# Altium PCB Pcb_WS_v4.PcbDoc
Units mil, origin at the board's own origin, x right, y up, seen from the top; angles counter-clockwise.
Board outline 3890 x 3890 mil, 2 copper layers (Top Layer, Bottom Layer); 75 components, 61 nets, 248 pads, 169 vias.
Unrouted connection lines stored in the file: 133.
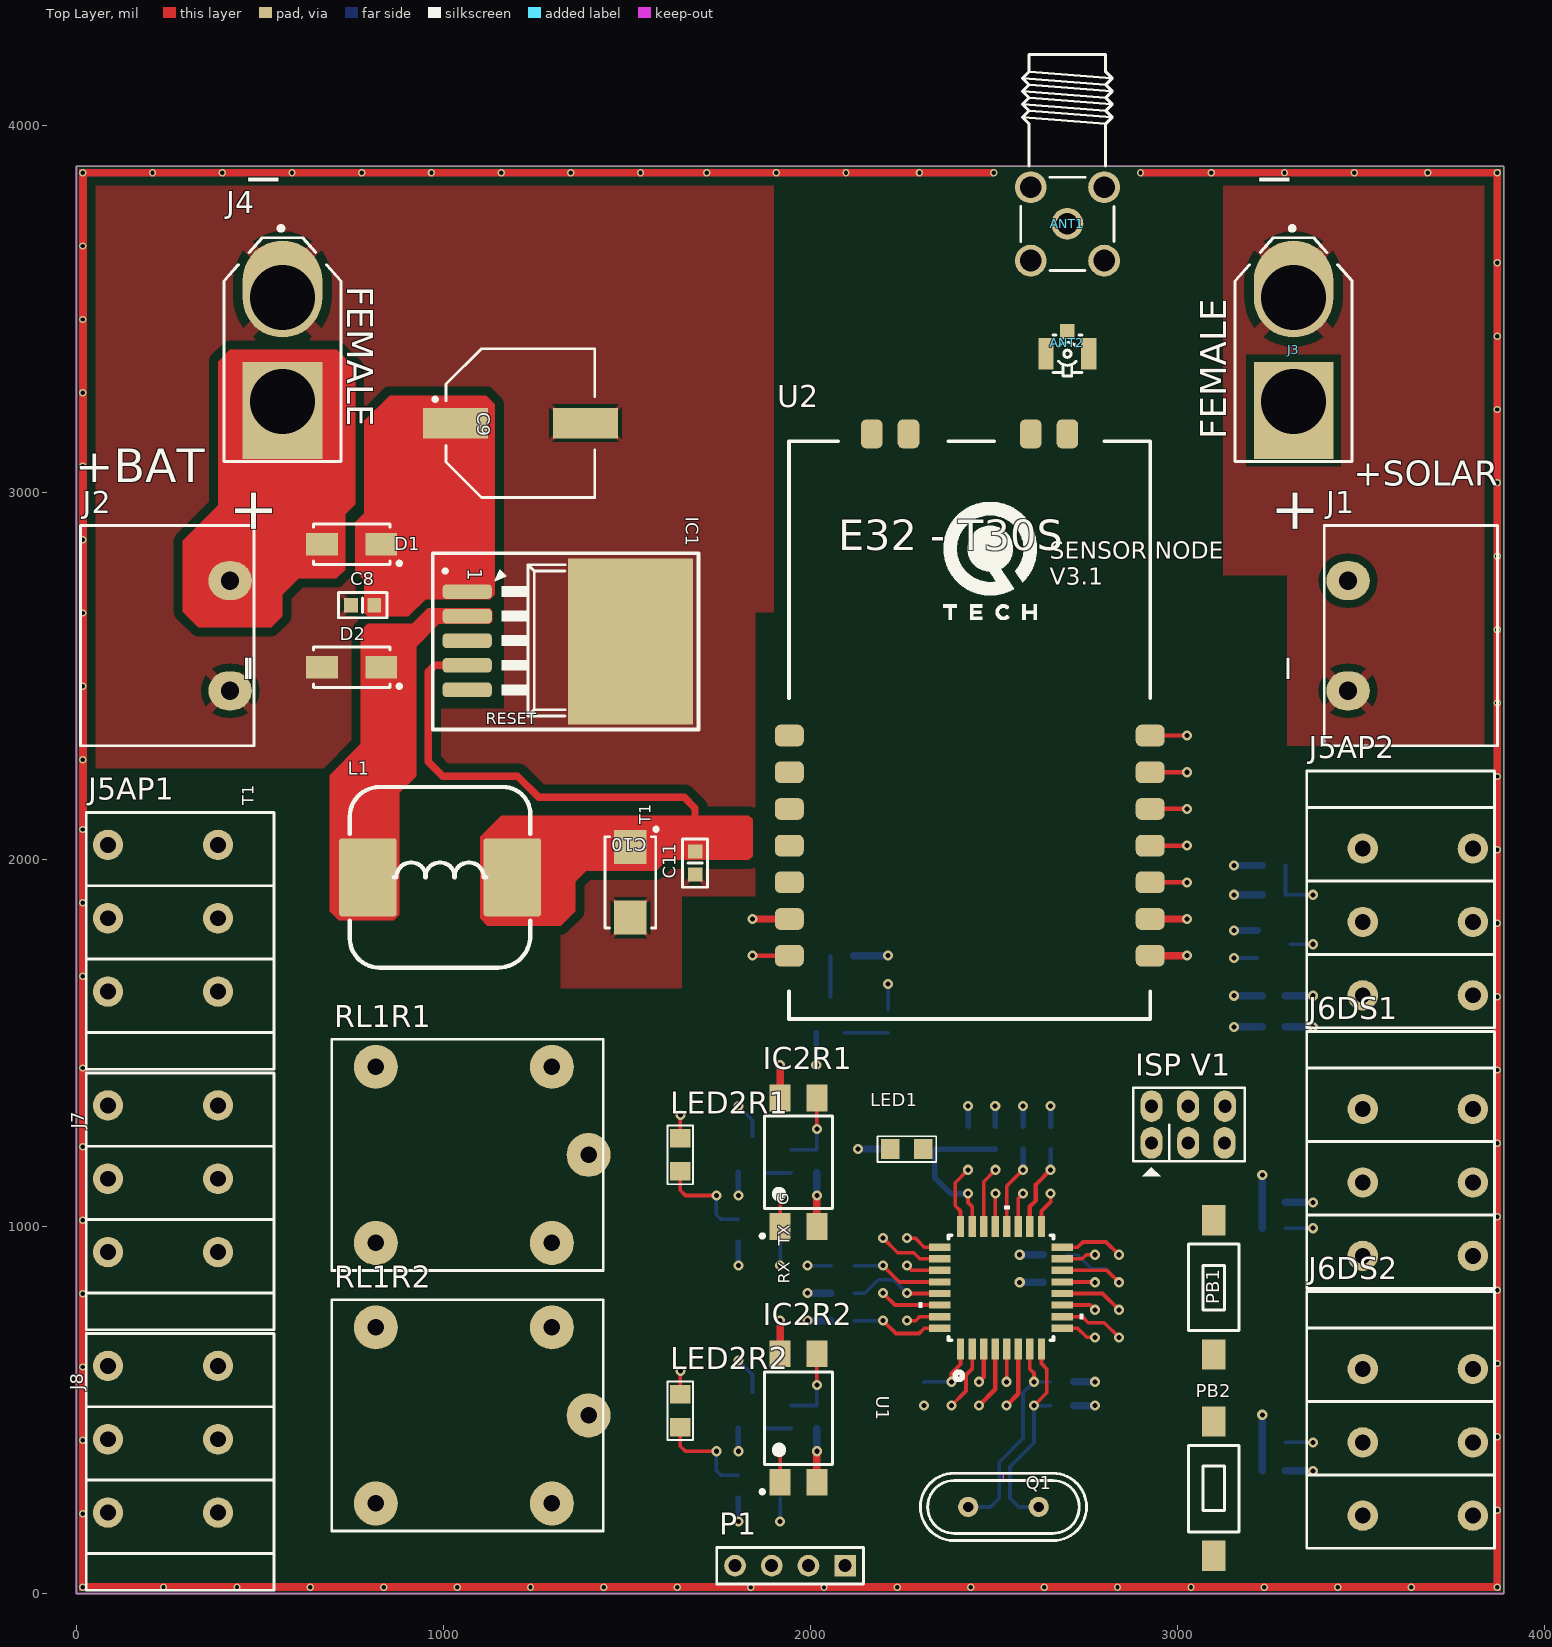
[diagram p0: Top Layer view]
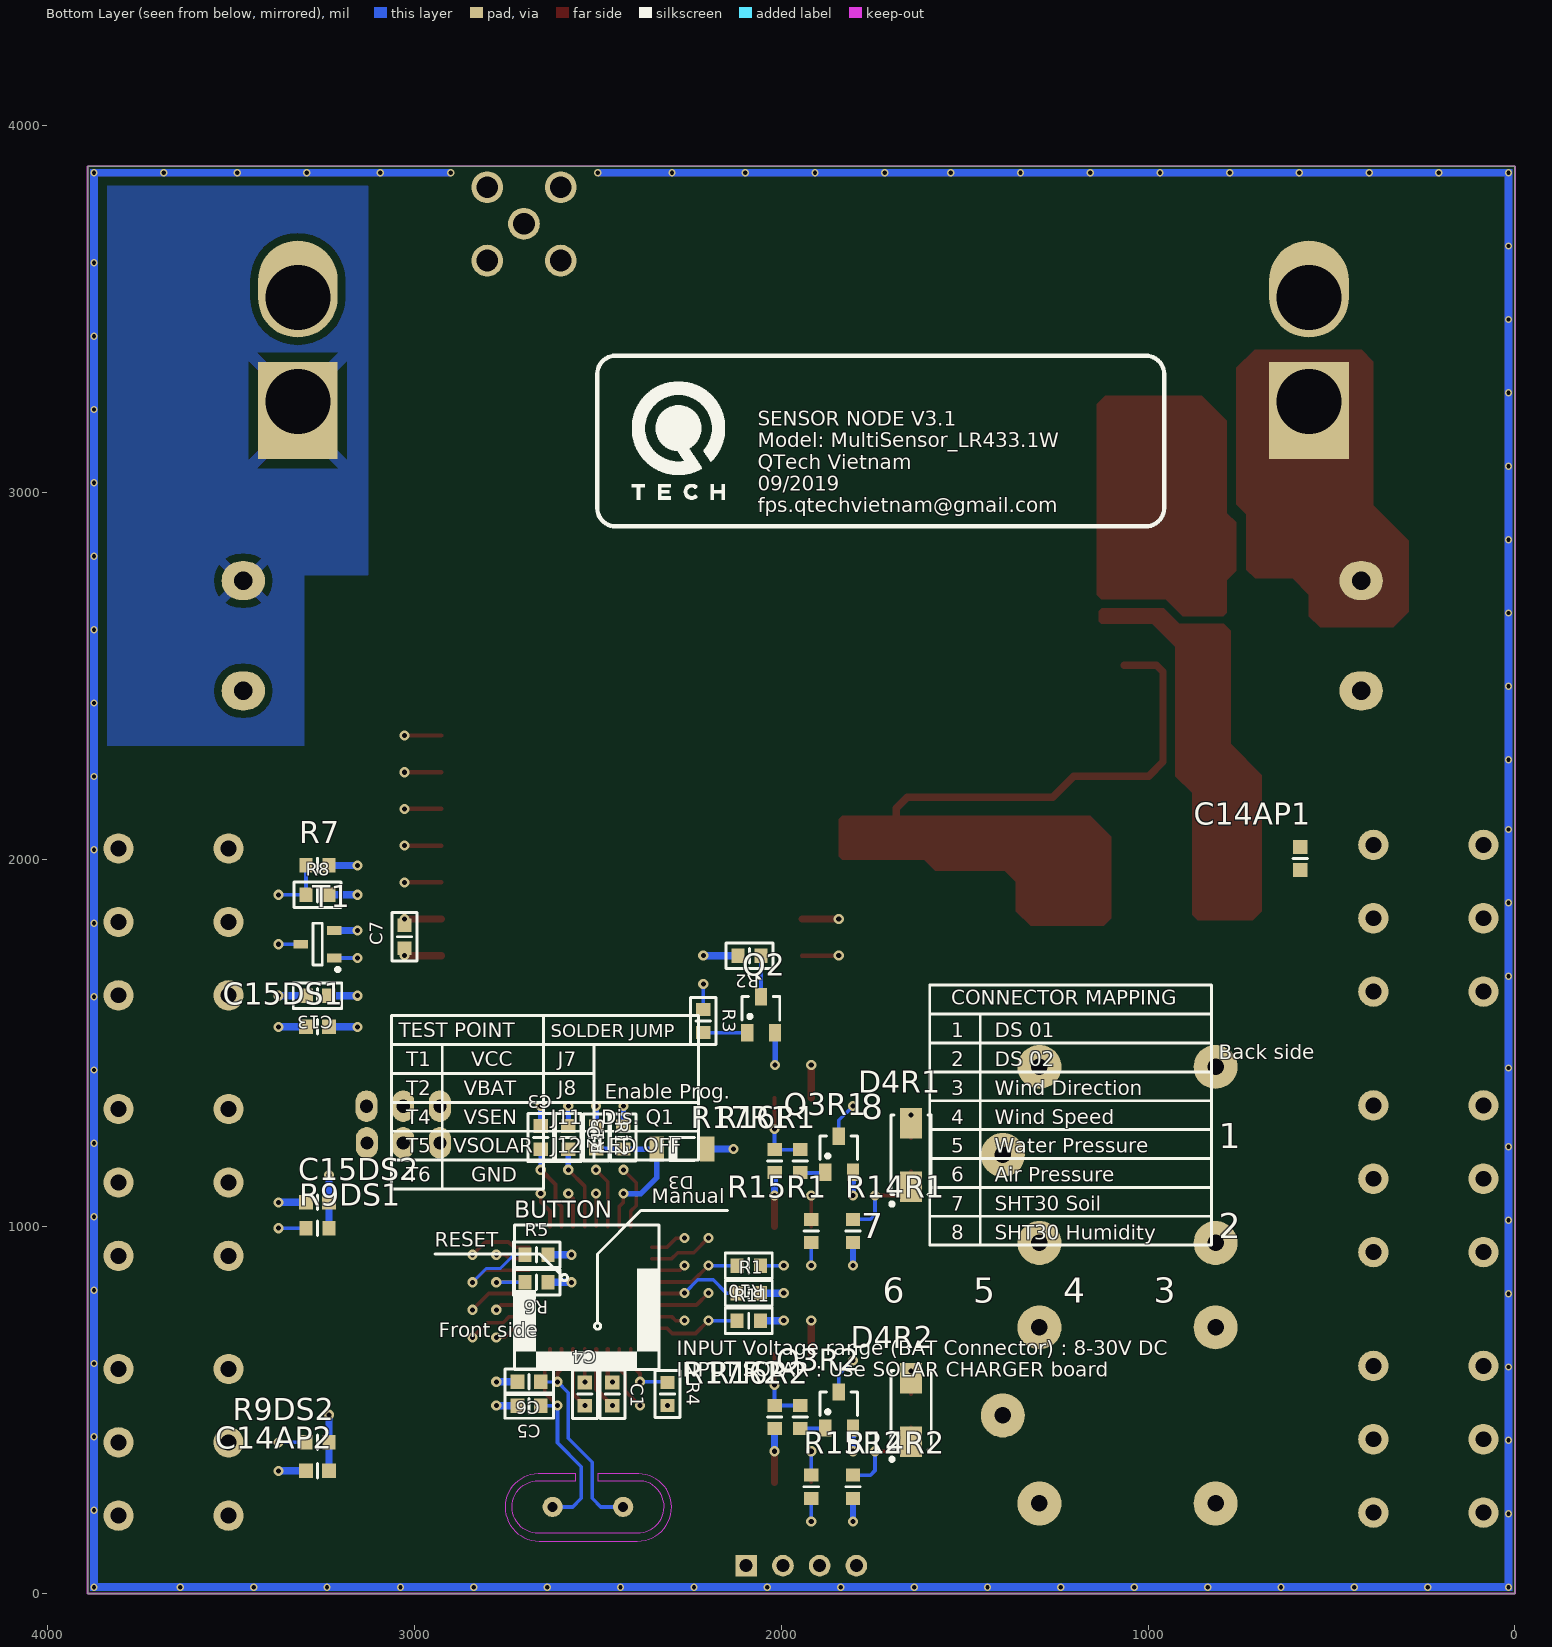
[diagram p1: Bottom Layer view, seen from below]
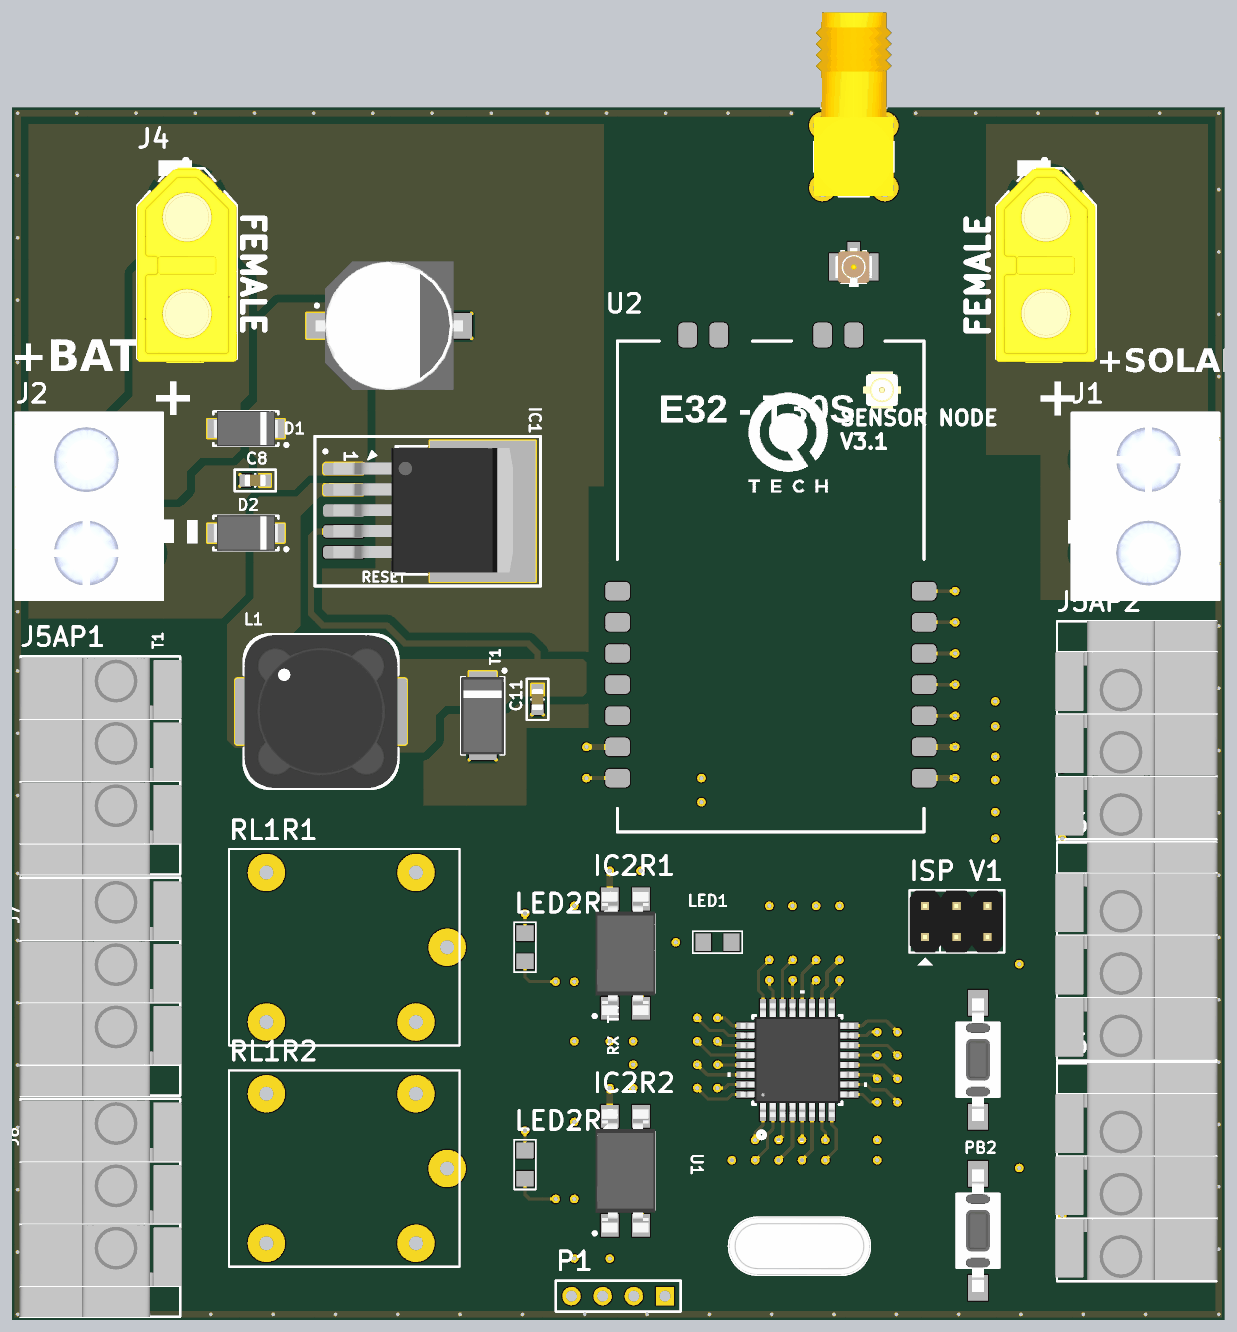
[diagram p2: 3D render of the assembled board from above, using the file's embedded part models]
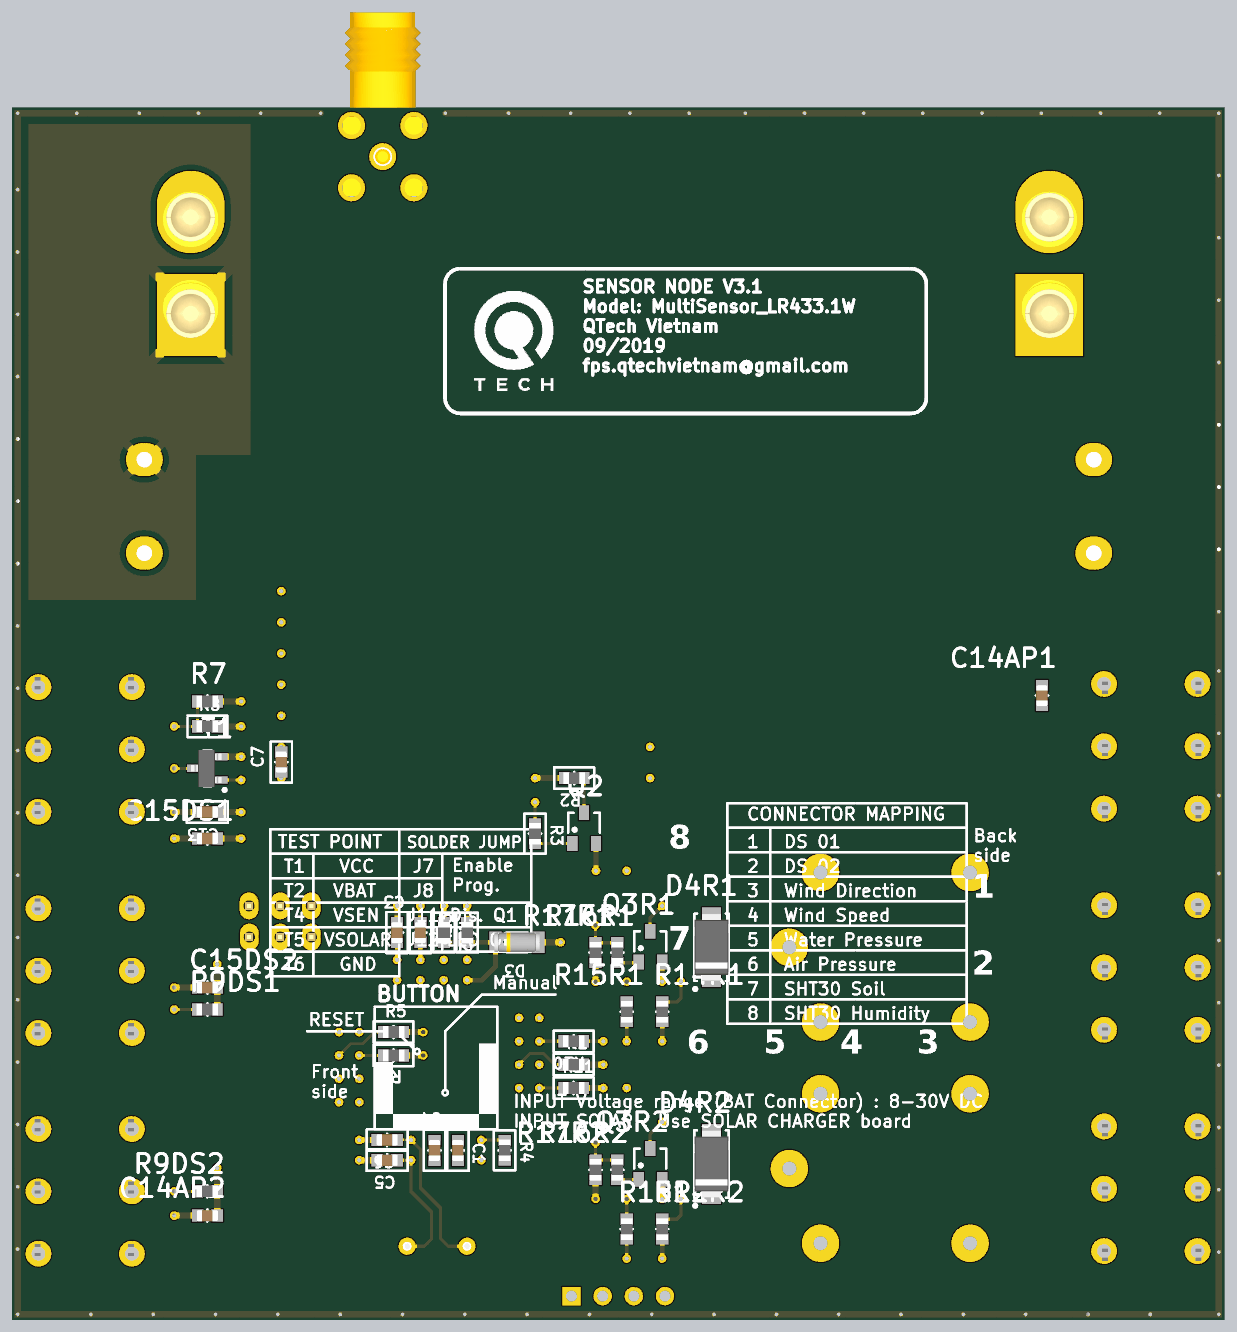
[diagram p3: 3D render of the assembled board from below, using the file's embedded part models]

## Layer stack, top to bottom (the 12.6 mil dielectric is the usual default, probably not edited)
Top Solder: solder mask 0.4, Solder Resist, Dk 3.5
Top Layer: signal copper 1.4
Dielectric 1: dielectric 12.6, FR-4, Dk 4.8
Bottom Layer: signal copper 1.4
Bottom Solder: solder mask 0.4, Solder Resist, Dk 3.5

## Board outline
0,0 0,3890 3890,3890 3890,0

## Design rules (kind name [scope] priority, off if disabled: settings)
Clearance Keep_Out [OnLayer('Keep-Out Layer')] p1: gap=5 ignorepadtopadclearanceinfootprint=FALSE
Clearance [All] p2: gap=10 ignorepadtopadclearanceinfootprint=FALSE except(15: SMDPad-Poly; 20: THPad-Poly; 25: Track-Poly Poly-Poly Poly-Region)
ComponentClearance KF-conn_Clearance [InComponentClass('KF_conn') vs InComponentClass('KF_conn')] p1: gap=5 collisioncheckmode=3 verticalgap=0 showdistances=FALSE
ComponentClearance HS_Comp_Clearance [InComponentClass('HS_Comp') vs IsComponent] p2: gap=165 collisioncheckmode=3 verticalgap=0 showdistances=FALSE
ComponentClearance IC_Comp_Clearance [InComponentClass('IC_Comp') vs IsComponent] p3: gap=150 collisioncheckmode=3 verticalgap=0 showdistances=FALSE
ComponentClearance conn-th_Clearance [InComponentClass('conn-th') vs IsComponent and not InComponentClass('conn-th')] p4: gap=150 collisioncheckmode=3 verticalgap=0 showdistances=FALSE
ComponentClearance chip-ge_Clearance [InComponentClass('chip-ge') vs InAnyComponent] p5: gap=75 collisioncheckmode=3 verticalgap=0 showdistances=FALSE
ComponentClearance chip-0603_Clearance [InComponentClass('chip-0603') vs IsComponent] p6: gap=25 collisioncheckmode=3 verticalgap=0 showdistances=FALSE
PolygonConnect [All] p1: thpad.connectstyle=Relief thpad.reliefconductorwidth=13.78 thpad.reliefentries=4 thpad.polygonreliefangle="45 Angle" thpad.airgapwidth=10 smdpad.connectstyle=Relief smdpad.reliefconductorwidth=11.81 smdpad.reliefentries=4 smdpad.polygonreliefangle="45 Angle" smdpad.airgapwidth=10 via.connectstyle=Direct via.reliefconductorwidth=10 via.reliefentries=4 via.polygonreliefangle="90 Angle" via.airgapwidth=10
RoomDefinition Top_Level [InComponentClass('Top_Level')] p1: confinementstyle=ConfineIn formatcopy=TRUE lockcomponents=FALSE outline -1409.14,-1234.46 590.86,-1234.46 590.86,-234.46 -1409.14,-234.46
RoomDefinition R2 [InComponentClass('R2')] p2: confinementstyle=ConfineIn formatcopy=TRUE lockcomponents=FALSE outline -1409.14,-1234.46 590.86,-1234.46 590.86,-234.46 -1409.14,-234.46
RoomDefinition R1 [InComponentClass('R1')] p3: confinementstyle=ConfineIn formatcopy=TRUE lockcomponents=FALSE outline -1409.14,-1234.46 590.86,-1234.46 590.86,-234.46 -1409.14,-234.46
RoomDefinition PWR [InComponentClass('PWR')] p4: confinementstyle=ConfineIn formatcopy=TRUE lockcomponents=FALSE outline -1409.14,-1234.46 590.86,-1234.46 590.86,-234.46 -1409.14,-234.46
RoomDefinition Main [InComponentClass('Main')] p5: confinementstyle=ConfineIn formatcopy=TRUE lockcomponents=FALSE outline -1409.14,-1234.46 590.86,-1234.46 590.86,-234.46 -1409.14,-234.46
RoomDefinition Lora [InComponentClass('Lora')] p6: confinementstyle=ConfineIn formatcopy=TRUE lockcomponents=FALSE outline -1409.14,-1234.46 590.86,-1234.46 590.86,-234.46 -1409.14,-234.46
RoomDefinition DS2 [InComponentClass('DS2')] p7: confinementstyle=ConfineIn formatcopy=TRUE lockcomponents=FALSE outline -1409.14,-1234.46 590.86,-1234.46 590.86,-234.46 -1409.14,-234.46
RoomDefinition DS1 [InComponentClass('DS1')] p8: confinementstyle=ConfineIn formatcopy=TRUE lockcomponents=FALSE outline -1409.14,-1234.46 590.86,-1234.46 590.86,-234.46 -1409.14,-234.46
RoomDefinition AP2 [InComponentClass('AP2')] p9: confinementstyle=ConfineIn formatcopy=TRUE lockcomponents=FALSE outline -1409.14,-1234.46 590.86,-1234.46 590.86,-234.46 -1409.14,-234.46
RoomDefinition AP1 [InComponentClass('AP1')] p10: confinementstyle=ConfineIn formatcopy=TRUE lockcomponents=FALSE outline -1409.14,-1234.46 590.86,-1234.46 590.86,-234.46 -1409.14,-234.46
RoutingVias [All] p1: holewidth=13.78 width=27.56 viastyle="Through Hole" minholewidth=11.81 minwidth=23.62 maxholewidth=19.68 maxwidth=39.37
ShortCircuit [All] p1: allowed=TRUE
SolderMaskExpansion [All] p1: expansion=4 istentingtop=FALSE
Width [All] p1: maxlimit=196.85 minlimit=8 preferedwidth=10
28 further rules are at their usual default settings.

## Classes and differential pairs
component class KF_conn: J5AP1 J5AP2 J6DS1 J6DS2 J7 J8
component class HS_Comp: ANT1 ANT2 Q1
component class IC_Comp: IC1 IC2R1 IC2R2 L1 U1 U2
component class chip-ge: C9 C10 D1 D2 D4R1 D4R2
component class conn-th: "ISP V1" J1 J2 J3 J4 J5AP1 J5AP2 J6DS1 J6DS2 J7 J8 P1 PB1 PB2 RL1R1 RL1R2
component class chip-0603: C1 C2 C3 C4 C5 C6 C7 C8 C11 C13 C14AP1 C14AP2 C15DS1 C15DS2 D3 LED1 LED2R1 LED2R2 Q2 Q3R1 Q3R2 R1 R2 R3 R4 R5 R6 R7 R8 R9DS1 R9DS2 R10 R11 R12 R13 R14R1 R14R2 R15R1 R15R2 R16R1 R16R2 R17R1 R17R2 T1
channel class Sensor_DS18b20_1Wire: DS1 DS2
channel class Sensor_AirPressure_1Wire: AP1 AP2
channel class Relay: R1 R2
component class Top_Level: D3 J7 J8 LED1 P1 PB2 R10 R11 R12 R13
component class R2: D4R2 IC2R2 LED2R2 Q3R2 R14R2 R15R2 R16R2 R17R2 RL1R2
component class R1: D4R1 IC2R1 LED2R1 Q3R1 R14R1 R15R1 R16R1 R17R1 RL1R1
component class Main: C1 C2 C3 C4 C5 C6 "ISP V1" PB1 Q1 R1 U1
component class Lora: ANT1 ANT2 C7 Q2 R2 R3 R4 R5 R6 U2
component class DS2: C15DS2 J6DS2 R9DS2
component class DS1: C15DS1 J6DS1 R9DS1
component class AP2: C14AP2 J5AP2
component class AP1: C14AP1 J5AP1
component class PWR: C8 C9 C10 C11 C13 D1 D2 IC1 J1 J2 J3 J4 L1 R7 R8 T1

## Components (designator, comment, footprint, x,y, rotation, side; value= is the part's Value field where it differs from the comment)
ANT1 "Coax_1Female_1Shield" "HUBER-SUHNER_85 SMA-50-0-101/111 NE" 2700.83,3733 r90 top
ANT2 "U.FL" HIROSE_U.FL-R-SMT-1(10) 2700.83,3379 r180 top
C1 "100nF" CAPC1608X87N 2459.61,543.68 r90 bottom
C2 "100nF" CAPC1608X87N 2580,1242.82 r270 bottom
C3 "100nF" CAPC1608X87N 2655,1242.82 r90 bottom
C4 "100nF" CAPC1608X87N 2534.61,543.68 r90 bottom
C5 "100nF" CAPC1608X87N 2686.8,512.18 r0 bottom value=22pF
C6 "100nF" CAPC1608X87N 2686.8,577.18 r0 bottom value=22pF
C7 "100nF" CAPC1608X87N 3026.43,1790 r270 bottom
C8 "100nF" CAPC1608X87N 780,2693.89 r180 top
C9 "470uF" CAPAE1030X1020N 1210,3190 r0 top
C10 "100uF" CAPMP6032X280N 1510,1938.49 r270 top
C11 "100nF" CAPC1608X87N 1686,1991 r270 top
C13 "100nF" CAPC1608X87N 3263.5,1629.46 r180 bottom
C14AP1 "100nF" CAPC1608X87N 585,2003.5 r90 bottom (schematic designator C14)
C14AP2 "100nF" CAPC1608X87N 3263.5,334.46 r180 bottom (schematic designator C14)
C15DS1 "100nF" CAPC1608X87N 3263.5,1544.46 r0 bottom (schematic designator C15)
C15DS2 "100nF" CAPC1608X87N 3263.5,1066.31 r180 bottom (schematic designator C15)
D1 "SS16" DIOM5127X229N 750,2860 r180 top
D2 "SS16" DIOM5127X229N 750,2525 r180 top
D3 "BZV55-B5V1" DIOMELF3515N 2269.96,1211.54 r180 bottom
D4R1 "BZG03C220" DIOM5326X230N 1645.86,1195.54 r90 bottom (schematic designator D4)
D4R2 "BZG03C220" DIOM5326X230N 1645.86,500 r90 bottom (schematic designator D4)
IC1 "LM2596" TO263-5 1065.04,2730.82 r270 top
IC2R1 "SFH6156-4" SOIC254P977X406-4N 1967.86,1175.54 r90 top (schematic designator IC2)
IC2R2 "SFH6156-4" SOIC254P977X406-4N 1967.86,478.26 r90 top (schematic designator IC2)
"ISP V1" "Connector 3x2" JP3x2 3030,1278.39 r0 top
J1 "CON KF7.62-2P" "CON KF7.62-2P" 3465.86,2610.54 r270 top locked
J2 "CON KF7.62-2P" "CON KF7.62-2P" 418.93,2610.54 r90 top locked
J3 "XT60-FM" XT60-FM 3317.31,3389.99 r270 top locked
J4 "XT60-FM" XT60-FM 561.41,3389.99 r270 top locked
J5AP1 "KF142V-3P" "CON KF142V-3P-5.08" 85.86,2040.54 r270 top (schematic designator J5)
J5AP2 "KF142V-3P" "CON KF142V-3P-5.08" 3805.86,1630.54 r90 top (schematic designator J5)
J6DS1 "KF142V-3P" "CON KF142V-3P-5.08" 3805.86,920.54 r90 top (schematic designator J6)
J6DS2 "KF142V-3P" "CON KF142V-3P-5.08" 3805.86,212.26 r90 top (schematic designator J6)
J7 "KF142V-3P" "CON KF142V-3P-5.08" 85.86,1330.54 r270 top
J8 "KF142V-3P" "CON KF142V-3P-5.08" 85.86,620.54 r270 top
L1 "33uH" L_SMD 794.25,1952 r90 top
LED1 "LED" L-0805 2263.39,1211.54 r180 top value="LED 3 ly Single Colour"
LED2R1 "LED" L-0805 1645.86,1195.54 r90 top value="LED 3 ly Single Colour" (schematic designator LED2)
LED2R2 "LED" L-0805 1645.86,498.26 r90 top value="LED 3 ly Single Colour" (schematic designator LED2)
P1 "Header 4" HDR1X4 2095,76 r180 top
PB1 "Push Button" PB_TYCO_FSMSM 3099.53,834.61 r270 top
PB2 "Push Button" PB_TYCO_FSMSM 3099.53,285.77 r90 top
Q1 "20MHz" XTAL_HC-49/U 2526.55,236.12 r0 top
Q2 "C1815" SOT23-3 2055.2,1577.8 r180 bottom
Q3R1 "C1815" SOT23-3 1842.86,1197.59 r180 bottom (schematic designator Q3)
Q3R2 "C1815" SOT23-3 1842.86,500.31 r180 bottom (schematic designator Q3)
R1 "10k" RESC1608X55N 2088.21,818.79 r0 bottom
R2 "10k" RESC1608X55N 2086.5,1738.49 r0 bottom value=4k7
R3 "10k" RESC1608X55N 2212.06,1560.29 r270 bottom value=1k
R4 "10k" RESC1608X55N 2309.61,543.68 r90 bottom value=1k
R5 "4k7" RESC1608X55N 2666.17,923.39 r180 bottom value=10k
R6 "4k7" RESC1608X55N 2666.17,848.39 r180 bottom value=10k
R7 "1k" RESC1608X55N 3263.5,1984.46 r0 bottom
R8 "10k" RESC1608X55N 3263.5,1904.46 r0 bottom
R9DS1 "4k7" RESC1608X55N 3263.5,995.77 r180 bottom (schematic designator R9)
R9DS2 "4k7" RESC1608X55N 3263.5,412.26 r180 bottom (schematic designator R9)
R10 "10k" RESC1608X55N 2088.21,893.79 r180 bottom value=200
R11 "10k" RESC1608X55N 2088.21,743.79 r0 bottom
R12 "10k" RESC1608X55N 2504.06,1242.82 r270 bottom value=2M
R13 "10k" RESC1608X55N 2430,1242.82 r90 bottom value=1M
R14R1 "1k" RESC1608X55N 1804.06,988.52 r90 bottom value=200 (schematic designator R14)
R14R2 "1k" RESC1608X55N 1804.06,291.24 r90 bottom value=200 (schematic designator R14)
R15R1 "1k" RESC1608X55N 1917.86,988.52 r90 bottom (schematic designator R15)
R15R2 "1k" RESC1608X55N 1917.86,291.24 r90 bottom (schematic designator R15)
R16R1 "1k" RESC1608X55N 1947.86,1178.52 r270 bottom value=200 (schematic designator R16)
R16R2 "1k" RESC1608X55N 1947.86,481.24 r270 bottom value=200 (schematic designator R16)
R17R1 "10k" RESC1608X55N 2017.86,1178.52 r90 bottom (schematic designator R17)
R17R2 "10k" RESC1608X55N 2017.86,481.24 r90 bottom (schematic designator R17)
RL1R1 "Relay 10A/12V" RL_SPDT_10A 1395.86,1195.54 r180 top value="Relay SPDT, 10A, 12V" (schematic designator RL1)
RL1R2 "Relay 10A/12V" RL_SPDT_10A 1395.86,485.54 r180 top value="Relay SPDT, 10A, 12V" (schematic designator RL1)
T1 "BSH203" SOT95P230X110-3N 3263.5,1769.74 r0 bottom
U1 "ATmega328-AU" 32A_ATM-M 2519.8,833.59 r90 top
U2 "E32-T30S" E32-T30S 2926.43,3140.85 r180 top

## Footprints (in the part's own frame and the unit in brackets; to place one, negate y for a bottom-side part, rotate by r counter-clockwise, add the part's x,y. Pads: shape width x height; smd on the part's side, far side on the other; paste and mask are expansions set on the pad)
32A_ATM-M [mil]
  rect 58x20 smd: 1(-167,110.24) 2(-167,78.74) 3(-167,47.24) 4(-167,15.75) 5(-167,-15.75) 6(-167,-47.24) 7(-167,-78.74) 8(-167,-110.24) 17(167,-110.24) 18(167,-78.74) 19(167,-47.24) 20(167,-15.75) 21(167,15.75) 22(167,47.24) 23(167,78.74) 24(167,110.24)
  rect 20x58 smd: 9(-110.24,-167) 10(-78.74,-167) 11(-47.24,-167) 12(-15.75,-167) 13(15.75,-167) 14(47.24,-167) 15(78.74,-167) 16(110.24,-167) 25(110.24,167) 26(78.74,167) 27(47.24,167) 28(15.75,167) 29(-15.75,167) 30(-47.24,167) 31(-78.74,167) 32(-110.24,167)
  silkscreen extent -250,-224 224,224, body extent -182,-182 182,182, height 47
CAPAE1030X1020N [mm] "Capacitor, Aluminium Electrolytric, 10.3mm L X 10.3mm W X 10.2mm H, IPC Medium Density"
  rect 4.5x2.1 smd: 1(-4.5,0) 2(4.5,0)
  silkscreen extent -6.02,-5.15 5.15,5.15, body extent -6,-5.25 6,5.25, height 10.2
CAPC1608X87N [mm] "Chip Capacitor, Body 1.6x0.8mm IPC Medium Density"
  rect 0.95x1 smd: 1(-0.8,0) 2(0.8,0)
  silkscreen extent -1.68,-0.87 1.68,0.87, body extent -0.87,-0.47 0.88,0.48, height 0.87
CAPMP6032X280N [mm] "Capacitor, Polarized, Molded  Body 6.0x3.2mm, IPC Medium Density"
  rect 2.35x2.25 smd: 1(-2.45,0) 2(2.45,0)
  silkscreen extent -3.8,-1.75 3.15,1.9, body extent -3.15,-1.75 3.15,1.75, height 2.8
"CON KF7.62-2P" [mm]
  oval 2.7x3 hole 1.26: 1(-3.81,0) 2(3.81,0)
  silkscreen extent -7.62,-1.65 7.62,10.35, body extent -7.62,-1.65 7.62,10.35, height 12.4
"CON KF142V-3P-5.08" [mm]
  round 2.1 hole 1.1: 1(0,7.62) 1(0,0) 2(5.08,7.62) 2(5.08,0) 3(10.16,7.62) 3(10.16,0)
  silkscreen extent -2.25,-1.5 15.53,11.5, body extent -2.14,-1.57 15.54,11.63, height 14.23
DIOM5127X229N [mm] "DO-214-AC/SMA Molded Diode, 2-Leads, Body 5.1x2.7mm, IPC Medium Density"
  rect 2.2x1.55 smd: 1(-2.05,0) 2(2.05,0)
  silkscreen extent -3.43,-1.4 2.65,1.45, body extent -2.67,-1.45 2.68,1.45, height 2.29
DIOM5326X230N [mm] "DO-214-AC/SMA Molded Diode, Body 5.3x2.6mm, IPC Medium Density"
  rect 2.1x1.55 smd: 1(-2.2,0) 2(2.2,0)
  silkscreen extent -3.52,-1.4 2.75,1.45, body extent -2.75,-1.4 2.75,1.4, height 2.3
DIOMELF3515N [mm] "SOD80C, MELF Diode, 2-Leads, Body 3.5x1.5mm, IPC Medium Density"
  rect 1x1.75 smd: 1(-1.75,0) 2(1.75,0)
  silkscreen extent -0.85,-0.8 0.85,0.8, body extent -1.85,-0.8 1.85,0.8, height 1.6
E32-T30S [mm] "Lora-EBYTE-21~30dBm-UART-SX1278-25x40mm"
  rrect50% 2x1.5 smd: 1(0,20.38) 2(0,22.92) 3(0,25.46) 4(0,28) 5(0,30.54) 6(0,33.08) 7(0,35.62) 8(24.98,35.62) 9(24.98,33.08) 10(24.98,30.54) 11(24.98,28) 12(24.98,25.46) 13(24.98,22.92) 14(24.98,20.38)
  rrect50% 1.5x2 smd: 15(19.27,-0.5) 16(16.73,-0.5) 17(8.27,-0.5) 18(5.73,-0.5)
  silkscreen extent 0,0 25,40, body extent 0,0 25,40, height 3.5
HDR1X4 [mm] "Connector; Header; 4 Position"
  rect 1.5x1.5 hole 0.9: 1(0,0)
  round 1.5 hole 0.9: 2(2.54,0) 3(5.08,0) 4(7.62,0)
  silkscreen extent -1.27,-1.27 8.89,1.27
HIROSE_U.FL-R-SMT-1(10) [mm] "Up to 6GHz Ultra Small Surface Mount Male Coaxial Connectors U.FL Series"
  rect 1x1.05 smd: 1(0,-1.525)
  rect 1.05x2.2 smd: 2(-1.475,0) 2(1.475,0)
  silkscreen extent -1,-1.3 1,1.55, body extent -1.5,-1.55 1.5,1.55, height 1.25
"HUBER-SUHNER_85 SMA-50-0-101/111 NE" [mm] "50 Ohm SMA Right Angle PCB Jack"
  round 2.2 hole 1.5: 1(0,0) 2(-2.54,-2.54) 2(-2.54,2.54) 2(2.54,-2.54) 2(2.54,2.54)
  silkscreen extent -3.23,-3.23 11.73,3.23, body extent -3.23,-3.23 11.73,3.23, height 9.6
JP3x2 [mil] "Connector 3x2"
  oval 60x86 hole 36: 1(-100,-50) 2(0,-50) 3(99,-50) 4(-100,50) 5(0,50) 6(100,50)
  silkscreen extent -150,-141 154,100, body extent -150,-100 150,100, height 335
L-0805 [mil] "Compoment SMD 80x50mil"
  rect 50x55 smd: 1(-45,0) 2(45,0)
  silkscreen extent -80,-35 80,35, body extent -50,-20 50,20, height 43
L_SMD [mm]
  rrect10% 5.4x4 smd mask+0.1: 1(0,0) 2(0,-10)
  silkscreen extent -6.25,-11.25 6.25,1.25, body extent -6.25,-11.25 6.25,1.25, height 6.7
PB_TYCO_FSMSM [mm] "Body 3.5x6.0mm, Pushbutton Switch,  TYCO FSMSM Serie"
  rect 2.1x1.6 smd: 1(-4.65,0) 2(4.65,0)
  silkscreen extent -3,-1.75 3,1.75, body extent -5,-1.75 5,1.75, height 4.3
RESC1608X55N [mm] "Chip Resistor, EIA 0603, Metric 1608, Body 1.6x0.8mm, IPC Medium Density"
  rect 0.9x1 smd: 1(-0.8,0) 2(0.8,0)
  silkscreen extent -1.63,-0.87 1.63,0.87, body extent -0.87,-0.47 0.88,0.48, height 0.55
RL_SPDT_10A [mil] "Relay SPDT, 5 pin, 10A,W 650mil, L 800mil, H 800mil"
  round 120 hole 45: 1(0,0) 2(580,240) 3(580,-240) 4(100,-240) 5(100,240)
  silkscreen extent -40,-315 700,315
SOIC254P977X406-4N [mm] "SOIC, 2.54mm pitch; 4 pin, 6.65mm W X 4.69mm L, IPC Medium Density"
  rect 1.85x1.45 smd: 1(-4.45,1.27) 2(-4.45,-1.27) 3(4.45,-1.27) 4(4.45,1.27)
  silkscreen extent -5.22,-2.35 3.2,2.62, body extent -5.01,-2.41 5.02,2.42, height 4.06
SOT23-3 [mm] "SOT 23"
  rect 0.85x1.2 smd: 1(-0.94,-1.245) 2(0.985,-1.25) 3(0.005,1.25)
  silkscreen extent -1.29,-0.38 1.31,1.25, body extent -1.5,-1.5 1.52,1.5, height 1.27
SOT95P230X110-3N [mm] "SOT23, 3 pin, Pitch 0.95mm - 1.3mm W X 2.9mm L X 1.1mm H, IPC Medium Density"
  rect 1x0.6 smd: 1(-1.15,0.95) 2(-1.15,-0.95) 3(1.15,0)
  silkscreen extent -1.52,-1.45 0.33,1.87, body extent -1.17,-1.5 1.33,1.5, height 1.1
TO263-5 [mm]
  rrect50% 1x3.4 smd: 1(0,0) 2(1.7,0) 4(5.1,0) 5(6.8,0)
  rrect50% 1x3.4 smd mask+0: 3(3.4,0)
  rect 11.5x8.634 smd: 6(3.45,11.302)
  silkscreen extent -2.66,-2.38 9.54,16.02, body extent -1.71,-0.87 8.45,13.77, height 4.57
XT60-FM [mm]
  oval 6.716x5.516 hole 4.5 copper offset -0.6,0: 1(-3.6,0)
  rect 6.716x5.516 hole 4.5 copper offset 0.6,0: 2(3.6,0)
  silkscreen extent -8.55,-4.05 7.75,4.05, body extent -7.81,-4.07 8.12,4.06, height 15.5
XTAL_HC-49/U [mm] "HC-49/U Leaded Cristal, Body 11.05x4.8mm; Pitch 4.88mm"
  round 1.4 hole 0.7: 1(-2.44,0) 2(2.44,0)
  silkscreen extent -5.75,-2.33 5.75,2.33, body extent -5.75,-2.33 5.75,2.33, height 3.5

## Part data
ANT1: library part HUBER-SUHNER_85_SMA-50-0-101/111_NE, Manufacturer=HUBER+SUHNER, Manufacturer Part Number=85_SMA-50-0-101/111_NE
ANT2: library part HIROSE_U.FL-R-SMT-1(10), Manufacturer="HIROSE (HRS)", Manufacturer Part Number=U.FL-R-SMT-1(10)
C1 C2 C3 C4 C7 C8 C11 C13 C14AP1 C14AP2 C15DS1 C15DS2: library part CC0603_100NF_50V_10%_X7R, "Non-polarised capacitor", Case=0603, Manufacturer=GENERIC, Manufacturer1 ComponentHeight=0.87mm, Manufacturer1 Example=PHYCOMP, Manufacturer1 Part Number=223858615649, Tolerance=±10%, Voltage=50V
C5 C6: library part CC0603_22PF_50V_5%_NP0, "Non-polarised capacitor", Case=0603, Manufacturer=GENERIC, Manufacturer1 ComponentHeight=0.87mm, Manufacturer1 Example=PHYCOMP, Manufacturer1 Part Number=223886715229, Tolerance=±5%, Voltage=50V
C9: library part CAE1030-1020_470UF_25V_20%, "Polarised capacitor", Case=G, Manufacturer=GENERIC, Manufacturer1 ComponentHeight=10.2mm, Manufacturer1 Example=PANASONIC, Manufacturer1 Part Number=EEEFK1E471AP, Tolerance=±20%, Voltage=25V
C10: library part CTE6032-28_100UF_6.3V_10%_LESR0075, "Polarised capacitor", Case=C, Manufacturer=GENERIC, Manufacturer1 ComponentHeight=2.8mm, Manufacturer1 Example=AVX, Manufacturer1 Part Number=TPSC107K006R0075, Tolerance=±10%, Voltage=6.3V
D1 D2: "Schottky Diode", Case=DO-214AC, Manufacturer="VISHAY GENERAL SEMICONDUCTOR", Power=1A, Voltage=60V
D3: "Zener Diode", Case=SOD-80C, Manufacturer="NXP SEMICONDUCTORS", Power=500mW, Voltage=5V1
D4R1 D4R2: "Zener Diode", Case=DO-214AC, Manufacturer="VISHAY SEMICONDUCTOR", Power=1.25W, Voltage=220V
IC1: library part LM2596-5V
IC2R1 IC2R2: "Single Optocoupler", Case=SOIC4, Manufacturer="VISHAY SEMICONDUCTORS"
"ISP V1": library part JP3x2
J3 J4: Package="Package Analog Devices"
J5AP1 J5AP2 J6DS1 J6DS2 J7 J8: library part "CON KF142V-3P-5.08", "CON KF142V-3P-5.08"
L1: library part "L_SMD 33uH"
LED1 LED2R1 LED2R2: "LED Single colour Green and Red"
P1: "Header, 4-Pin"
PB1 PB2: "Push-Button Switch SPDT", Manufacturer="TYCO ELECTRONICS", Manufacturer Part Number="FSMSM or 1437566-3", Part Number=PB_TYCO_FSMSM
Q1: library part XTAL_20MHZ_AEL_HC-49/U, "Quartz Crystal", Manufacturer="AEL CRYSTALS", Manufacturer Part Number=X20M000000L010
Q2 Q3R1 Q3R2: library part 2SC1815, PSpiceTemplate="Q^@REFDES %c %b %e @MODEL"
R1 R5 R6 R8 R11 R17R1 R17R2: library part R0603_10K_1%_0.1W_100PPM, "Resistor - 1%", Case=0603, Manufacturer=GENERIC, Manufacturer1 ComponentHeight=0.55mm, Manufacturer1 Example="NIC COMPONENT", Manufacturer1 Part Number=NRC06F1002TRF, Power=0.1W, Tolerance=±1%
R2 R9DS1 R9DS2: library part R0603_4K7_1%_0.1W_100PPM, "Resistor - 1%", Case=0603, Manufacturer=GENERIC, Manufacturer1 ComponentHeight=0.55mm, Manufacturer1 Example="NIC COMPONENT", Manufacturer1 Part Number=NRC06F4701TRF, Power=0.1W, Tolerance=±1%
R3 R4 R7 R15R1 R15R2: library part R0603_1K_1%_0.1W_100PPM, "Resistor - 1%", Case=0603, Manufacturer=GENERIC, Manufacturer1 ComponentHeight=0.55mm, Manufacturer1 Example="NIC COMPONENT", Manufacturer1 Part Number=NRC06F1001TRF, Power=0.1W, Tolerance=±1%
R10 R14R1 R14R2 R16R1 R16R2: library part R0603_200R_1%_0.1W_100PPM, "Resistor - 1%", Case=0603, Manufacturer=GENERIC, Manufacturer1 ComponentHeight=0.55mm, Manufacturer1 Example="NIC COMPONENT", Manufacturer1 Part Number=NRC06F2000TRF, Power=0.1W, Tolerance=±1%
R12: library part R0603_2M_1%_0.1W_100PPM, "Resistor - 1%", Case=0603, Manufacturer=GENERIC, Manufacturer1 ComponentHeight=0.55mm, Manufacturer1 Example="NIC COMPONENT", Manufacturer1 Part Number=NRC06F2004TRF, Power=0.1W, Tolerance=±1%
R13: library part R0603_1M_1%_0.1W_100PPM, "Resistor - 1%", Case=0603, Manufacturer=GENERIC, Manufacturer1 ComponentHeight=0.55mm, Manufacturer1 Example="NIC COMPONENT", Manufacturer1 Part Number=NRC06F1004TRF, Power=0.1W, Tolerance=±1%
RL1R1 RL1R2: library part "Relay 1", "Relay SPDT,10A - 12VDC 5 Pin"
T1: "P-CHANNEL MOSFET WITH DIODE", Case=SOT23-3, Manufacturer="NXP SEMICONDUCTORS"
U1: "8-bit AVR Microcontroller, 32KB Flash, 1KB EEPROM, 2KB SRAM, 32-pin TQFP, Industrial Grade (-40°C to 85°C)", Supplier Part Number 1=ATMEGA328-AU-ND
U2: library part E32-433T30S, "Lora Ebyte E32-T30S Module"

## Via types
v1: diameter 27.56, hole 13.78, Top Layer to Bottom Layer, 93 vias
v2: diameter 20, hole 11.81, Top Layer to Bottom Layer, tented both sides, 76 vias

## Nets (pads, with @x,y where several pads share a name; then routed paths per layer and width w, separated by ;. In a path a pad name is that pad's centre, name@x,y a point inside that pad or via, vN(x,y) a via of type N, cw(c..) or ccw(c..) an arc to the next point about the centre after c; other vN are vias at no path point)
ANT_M: U2.18
ANT_M1: ANT1.1 ANT2.1
AREF: C2.2 U1.20 | length 229.1
  Top Layer w10: U1.20 2535.55,1110.55 v1(2580,1155)
  Bottom Layer w15: v1(2580,1155) C2.2
AUX: U1.2 U2.5 | length 277.8
  Top Layer w10: v1(2384.61,512.18) 2424.61,552.18 2424.61,595.81 2441.06,612.26 U1.2
  Top Layer w12: U2.5 v1(3026.43,1938.49)
BAT-VSEN: C8.1 C9.1 D1.1 IC1.1 R12.1 | length 54.1
  Bottom Layer w15: R12.1 v1(2504.06,1328.39)
BAT-VSEN-Q: D3.1 R12.2 R13.1 U1.23 | length 446.5
  Top Layer w10: v1(2430,1090) 2430,1065.98 2441.06,1054.92 U1.23
  Bottom Layer w15: v1(2430,1090) 2382.4,1090 2338.86,1133.54 D3.1 2339.07,1211.32 R13.1 R12.2
CLOSE1: J7.3 RL1R1.2
CLOSE2: J8.3 RL1R2.2
COM1: J7.2 RL1R1.1
COM2: J8.2 RL1R2.1
DATA-AP1: J5AP1.2 U1.24 | length 174.9
  Top Layer w10: U1.24 2409.57,1042.43 2395,1057 2395,1120 v1(2430,1155)
DATA-AP2: J5AP2.2 U1.25 | length 99.7
  Top Layer w10: v1(2263.39,968.79) 2286,968.79 2310.96,943.83 U1.25
DATA-DS1: J6DS1.2 R9DS1.1 U1.10 | length 252.8
  Top Layer w10: U1.10 2741.13,754.85 2757.59,738.39 2801.21,738.39 v1(2841.21,698.39)
  Bottom Layer w10: R9DS1.1 v1(3370,995.77)
DATA-DS2: J6DS2.2 R9DS2.1 U1.9 | length 174.7
  Top Layer w10: U1.9 2728.65,723.35 2753.61,698.39 v1(2776.21,698.39)
  Bottom Layer w10: R9DS2.1 v1(3370,412.26)
GND: "ISP V1.5" ANT1.2 ANT2.2 C1.2 C2.1 C3.2 C4.2 C5.2 C6.2 C7.2 C8.2 C9.2 C10.2 C11.2 C13.2 C14AP1.1 C14AP2.1 C15DS1.1 C15DS2.1 D2.2 D3.2 IC1.3 IC1.5 IC1.6 IC2R1.2 IC2R2.2 J2.1 J4.1 J5AP1.3 J5AP2.3 J6DS1.3 J6DS2.3 LED1.2 P1.4 PB1.2 PB2.2 Q2.2 Q3R1.2 Q3R2.2 R4.1 R5.2 R6.2 R7.1 R13.2 R17R1.1 R17R2.1 U1.3 U1.5 U1.21 U2.7 U2.9 U2.15 U2.16 U2.17 | length 1839.8
  Top Layer w9.84: U1.21 2504.06,1089.06 v1(2505,1090) ; v1(2534.61,577.18) 2535.55,578.13 U1.5
  Top Layer w12: v1(2459.61,577.18) 2472.56,590.13 U1.3
  Top Layer w20: v1(1842.96,1838.49) U2.9 ; IC2R2.2 v1(2017.86,387.87) ; IC2R1.2 v1(2017.86,1085.15) ; U2.7 v1(3026.43,1738.49)
  Bottom Layer w15: v1(1804.06,387.87) Q3R2.2 ; v1(1804.06,1085.14) Q3R1.2 ; v1(2016.4,1441.07) Q2.2 ; R13.2 v1(2430,1328.39) ; C2.1 v1(2580,1328.39) ; C3.2 v1(2655,1328.39)
  Bottom Layer w20: v1(2017.86,387.87) R17R2.1 ; v1(2017.86,1085.15) R17R1.1 ; v1(2129.76,1211.54) D3.2 ; v1(2570.81,848.39) R6.2 ; v1(2570.81,923.39) R5.2 ; C5.2 v1(2776.21,512.18) ; C6.2 v1(2776.21,577.18) ; v1(3155,1544.46) C15DS1.1 ; v1(3155,1629.46) C13.2 ; v1(3155,1984.46) R7.1 ; C14AP2.1 v1(3370,334.46) ; C15DS2.1 v1(3370,1066.31)
  other v1: 2309.61,512.18
  other v2: 17.5,17.5 237.5,17.5 437.5,17.5 637.5,17.5 837.5,17.5 1037.5,17.5 1237.5,17.5 1437.5,17.5 1637.5,17.5 1837.5,17.5 2037.5,17.5 2237.5,17.5 2437.5,17.5 2637.5,17.5 2837.5,17.5 3037.5,17.5 3237.5,17.5 3437.5,17.5 3637.5,17.5 3872.5,17.5 17.5,217.5 3872.5,227 17.5,417.5 3872.5,427 17.5,617.5 3872.5,627 17.5,817.5 3872.5,827 17.5,1017.5 3872.5,1027 17.5,1217.5 3872.5,1227 3872.5,1427 17.5,1432.5 3872.5,1627 17.5,1682.5 3872.5,1827 17.5,1882.5 3872.5,2027 17.5,2082.5 3872.5,2227 17.5,2272.5 3872.5,2427 17.5,2472.5 3872.5,2627 17.5,2672.5 3872.5,2827 17.5,2872.5 3872.5,3027 17.5,3072.5 3872.5,3227 17.5,3272.5 3872.5,3427 17.5,3472.5 3872.5,3627 17.5,3672.5 17.5,3872.5 207.5,3872.5 397.5,3872.5 587.5,3872.5 777.5,3872.5 967.5,3872.5 1157.5,3872.5 1347.5,3872.5 1537.5,3872.5 1717.5,3872.5 1907.5,3872.5 2097.5,3872.5 2297.5,3872.5 2500,3872.5 2900,3872.5 3092.5,3872.5 3292.5,3872.5 3482.5,3872.5 3682.5,3872.5 3872.5,3872.5
GND-SOLAR: J1.2 J3.1
LED: R10.1 U1.28 | length 251.5
  Top Layer w10: v1(2198.39,893.79) 2242.84,849.34 U1.28
  Bottom Layer w10: R10.1 v1(2198.39,893.79)
M0: U1.11 U2.1 | length 194.8
  Top Layer w10: U1.11 2763.26,786.35 v1(2776.21,773.39)
  Top Layer w12: U2.1 v1(3026.43,2338.49)
M1: U1.12 U2.2 | length 272.8
  Top Layer w10: U1.12 2796.76,817.84 v1(2841.21,773.39)
  Top Layer w12: U2.2 v1(3026.43,2238.49)
MISO: "ISP V1.2" U1.16 | length 174.9
  Top Layer w10: U1.16 2728.65,943.83 2743.21,958.39 2806.21,958.39 v1(2841.21,923.39)
MOSI: "ISP V1.3" U1.15 | length 94
  Top Layer w10: U1.15 2741.13,912.33 2752.19,923.39 v1(2776.21,923.39)
NetD2_1: D2.1 IC1.2 L1.1
NetD4R1_2: D4R1.2 LED2R1.2 Q3R1.3 RL1R1.4 | length 160.8
  Top Layer w10: LED2R1.2 v1(1645.86,1303.81)
  Bottom Layer w10: v1(1804.06,1328.39) 1842.66,1289.8 Q3R1.3
NetD4R2_2: D4R2.2 LED2R2.2 Q3R2.3 RL1R2.4 | length 164.7
  Top Layer w10: LED2R2.2 v1(1645.86,606.53)
  Bottom Layer w10: v1(1804.06,635) 1842.66,596.4 Q3R2.3
NetIC2R1_1: IC2R1.1 R15R1.2 | length 84.8
  Top Layer w10: IC2R1.1 v1(1917.86,1085.15)
NetIC2R2_1: IC2R2.1 R15R2.2 | length 149.9
  Top Layer w10: IC2R2.1 v1(1917.86,387.87)
  Bottom Layer w10: R15R2.2 v1(1917.86,387.87)
NetLED1_1: LED1.1 R10.2 | length 63.9
  Bottom Layer w10: v1(1992.86,893.79) R10.2
NetLED2R1_1: LED2R1.1 R14R1.2 | length 273.2
  Top Layer w10: LED2R1.1 1645.86,1099.14 1659.86,1085.14 v1(1744.06,1085.14)
  Bottom Layer w10: v1(1744.06,1085.14) 1744.06,1032.6 1756.65,1020.01 R14R1.2
NetLED2R2_1: LED2R2.1 R14R2.2 | length 273.2
  Top Layer w10: LED2R2.1 1645.86,401.86 1659.86,387.87 v1(1744.06,387.87)
  Bottom Layer w10: v1(1744.06,387.87) 1744.06,335.32 1756.65,322.73 R14R2.2
NetQ2_1: Q2.1 R3.2 | length 119.9
  Bottom Layer w10: Q2.1 R3.2
NetQ3R1_1: Q3R1.1 R16R1.2 | length 68.4
  Bottom Layer w10: Q3R1.1@1879.86,1146.01 1946.85,1146.01 R16R1.2
NetQ3R2_1: Q3R2.1 R16R2.2 | length 68.7
  Bottom Layer w10: Q3R2.1 1881.43,449.74 R16R2.2
NetR7_2: R7.2 R8.2 T1.1 | length 218.2
  Bottom Layer w10: v1(3155,1732.33) T1.1 ; R7.2 R8.2 v1(3370,1904.46)
NetU1_19: U1.19 | length 94.8
  Top Layer w10: U1.19 2567.05,1077.05 v1(2580,1090)
NetU1_22: U1.22 | length 167.8
  Top Layer w10: U1.22 2472.56,1122.56 v1(2505,1155)
NetU2_10: U2.10
NetU2_11: U2.11
NetU2_12: U2.12
NetU2_13: U2.13
NetU2_14: U2.14
OPEN1: J7.1 RL1R1.3
OPEN2: J8.1 RL1R2.3
P5V-Main: "ISP V1.6" C1.1 C3.1 C4.1 C7.1 C10.1 C11.1 D4R1.1 D4R2.1 IC1.4 IC2R1.4 IC2R2.4 L1.2 P1.1 R1.1 R2.2 R8.1 R11.1 R14R1.1 R14R2.1 RL1R1.5 RL1R2.5 T1.2 U1.4 U1.6 U1.18 U2.6 | length 2599.8
  Top Layer w12: v1(2459.61,512.18) 2504.06,556.63 U1.4 ; v1(2534.61,512.18) 2567.05,544.62 U1.6 ; U1.18 2598.54,1054.92 2615,1071.38 2615,1115 v1(2655,1155)
  Top Layer w20: IC1.4 977.03,2530.03 959,2512 959,2267.02 998.02,2228 1202,2228 1259.72,2170.28 1656.15,2170.28 1686,2140.43 C11.1 ; IC2R2.4 v1(1917.86,743.79) ; IC2R1.4 v1(1917.86,1441.07) ; U2.6 v1(3026.43,1838.49)
  Bottom Layer w12: v1(2655,1155) C3.1
  Bottom Layer w15: v1(1804.06,196.51) R14R2.1 ; v1(1804.06,893.79) R14R1.1
  Bottom Layer w20: v1(1992.86,743.79) R11.1 ; v1(1992.86,818.79) R1.1 ; R2.2 v1(2212.06,1738.49) ; v1(3155,1807.14) T1.2 ; v1(3155,1904.46) R8.1
P5V-SEN: C13.1 C14AP1.2 C14AP2.2 C15DS1.2 C15DS2.2 J5AP1.1 J5AP2.1 J6DS1.1 J6DS2.1 R9DS1.2 R9DS2.2 T1.3 | length 509.6
  Bottom Layer w10: T1.3 v1(3370,1769.74)
  Bottom Layer w20: C14AP2.2 R9DS2.2 v1(3232.01,487.26) ; R9DS1.2 C15DS2.2 v1(3232.01,1141.31) ; C15DS1.2 v1(3370,1544.46) ; C13.1 v1(3370,1629.46)
P12V-BAT: D1.2 J2.2 J4.2
P16V-SOLAR: J1.1 J3.2
RESET-E32: R3.1 R4.2 U1.1 | length 245.9
  Top Layer w10: v1(2384.61,577.18) 2384.61,599.79 2409.57,624.75 U1.1
  Bottom Layer w9.84: R3.1@2212.06,1590.94 v1(2212.06,1661.26)
  Bottom Layer w10: R4.2 2311.61,577.18 v1(2384.61,577.18)
RL-CT-QR1: IC2R1.3 R16R1.1 R17R1.2 | length 210.7
  Top Layer w10: v1(2017.86,1265.93) IC2R1.3
  Bottom Layer w10: R16R1.1 R17R1.2 v1(2017.86,1265.93)
RL-CT-QR2: IC2R2.3 R16R2.1 R17R2.2 | length 210.7
  Top Layer w10: v1(2017.86,568.65) IC2R2.3
  Bottom Layer w10: R16R2.1 R17R2.2 v1(2017.86,568.65)
RL-CTL1: R15R1.1 U1.26 | length 241
  Top Layer w10: v1(2198.39,968.79) 2238.39,928.79 2282.02,928.79 2298.48,912.33 U1.26
  Bottom Layer w10: v1(1917.86,893.79) R15R1.1
RL-CTL2: R15R2.1 U1.27 | length 158
  Top Layer w10: v1(2263.39,893.79) 2276.35,880.83 U1.27
  Bottom Layer w10: v1(1917.86,196.51) R15R2.1
RST-E32: Q2.3 R2.1 U2.8 | length 211.5
  Top Layer w12: v1(1842.96,1738.49) U2.8
  Bottom Layer w10: Q2.3 R2.1
RST_MCU: "ISP V1.4" PB1.1 R1.2 U1.29 | length 263.5
  Top Layer w10: v1(2263.39,818.79) 2264.34,817.84 U1.29
  Bottom Layer w10: R1.2 2148.79,818.79 2185,855 2227.18,855 v1(2263.39,818.79)
RXD-E32: R6.1 U1.13 U2.3 | length 268.4
  Top Layer w10: U1.13 2775.27,849.34 v1(2776.21,848.39)
  Top Layer w12: U2.3 v1(3026.43,2138.49)
  Bottom Layer w10: R6.1 v1(2776.21,848.39)
RXM: P1.3 U1.30 | length 167.8
  Top Layer w10: v1(2198.39,818.79) 2230.83,786.35 U1.30
SCK: "ISP V1.1" U1.17 | length 99.7
  Top Layer w10: U1.17 2630.04,1042.43 2655,1067.39 v1(2655,1090)
TXD-E32: R5.1 U1.14 U2.4 | length 442.5
  Top Layer w10: U1.14 2808.77,880.83 v1(2841.21,848.39)
  Top Layer w12: U2.4 v1(3026.43,2038.49)
  Bottom Layer w8: R5.1 2728.31,923.39 2766.17,885.54 2804.07,885.54 v1(2841.21,848.39)
TXM: P1.2 U1.31 | length 94
  Top Layer w10: v1(2263.39,743.79) 2287.41,743.79 2298.48,754.85 U1.31
WAKE: PB2.1 R11.2 U1.32 | length 253.6
  Top Layer w10: v1(2198.39,743.79) 2233.39,708.79 2296.39,708.79 2310.96,723.35 U1.32
  Bottom Layer w10: R11.2 v1(2198.39,743.79)
XTAL1: C6.1 Q1.1 U1.7 | length 590.6
  Top Layer w10: U1.7 2598.54,612.26 2609.61,601.2 v1(2609.61,577.18)
  Bottom Layer w8: v1(2609.61,577.18) C6.1
  Bottom Layer w10: Q1.1 2491.32,236.12 2514.95,259.74 2514.95,358.04 2580,423.09 2580,547.57 v1(2609.61,577.18)
XTAL2: C5.1 Q1.2 U1.8 | length 587.9
  Top Layer w10: v1(2609.61,512.18) 2644.61,547.18 2644.61,612.26 2630.04,626.83 U1.8
  Bottom Layer w10: Q1.2 2568.17,236.12 2544.55,259.74 2544.55,345.77 2609.61,410.83 v1(2609.61,512.18) C5.1

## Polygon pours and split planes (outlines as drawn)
GND-SOLAR on Top Layer "GND-SOLAR_L01_P028" (solid, pour order 28): 3300,2775 3125,2775 3125,3862.5 3862.5,3862.5 3862.5,2310 3300,2310
GND on Top Layer "GND_L01_P027" (solid, remove dead copper, pour order 27): 27.5,2250 27.5,3862.5 1900,3862.5 1900,2675 1850,2675 1850,1900 1650,1900 1650,1650 650,1650 650,2250
no net on Top Layer "Top Layer-No Net" (solid, shelved, pour order 14): 1060.77,4984.95
no net on Top Layer "AutoNaming" (solid, shelved, pour order 22): -29.14,150.54
no net on Top Layer "AutoNaming" (solid, shelved, pour order 26): -29.14,150.54
P16V-SOLAR on Bottom Layer "P16V-SOLAR_L02_P029" (solid, pour order 29): 3300,2775 3125,2775 3125,3862.5 3862.5,3862.5 3862.5,2310 3300,2310

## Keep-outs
Top Layer:
  region: 2526.55,326 2662.31,326 cw(c2662.31,236.12) 2752.19,236.12 cw(c2659.08,236.12) 2659.07,143 2391.59,143 cw(c2391.59,236.12) 2298.48,236.12 cw(c2388.36,236.12) 2388.36,326 2526.55,326 2526.55,308.17 2374.48,308.17 ccw(c2394.88,236.12) 2320,236.12 ccw(c2392.12,236.12) 2392.12,164 2661.13,164 ccw(c2661.13,236.12) 2733.25,236.12 ccw(c2661.2,236.12) 2661.2,308.17 2526.55,308.17
Bottom Layer:
  region: 2560,326 2662.31,326 cw(c2662.31,236.12) 2752.19,236.12 cw(c2659.08,236.12) 2659.07,143 2391.59,143 cw(c2391.59,236.12) 2298.47,236.12 cw(c2388.36,236.12) 2388.36,326 2500,326 2500,308.17 2374.48,308.17 ccw(c2394.88,236.12) 2320,236.12 ccw(c2392.12,236.12) 2392.12,164 2661.13,164 ccw(c2661.13,236.12) 2733.25,236.12 ccw(c2661.2,236.12) 2661.2,308.17 2560,308.17
  region: 3864.91,2241.96
Keep-Out Layer:
  the board outline again, w5

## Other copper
Top Layer:
  region net BAT-VSEN: 785,2672.5 794.5,2663 905,2663 952,2710 1127.5,2710 1140,2722.5 1140,3242.01 1117.01,3265 853.72,3265 785,3196.28 785,2945 759.51,2919.51 759.51,2787.55 785,2762.06
  region net P12V-BAT: 290,2869.68 385.86,2965.54 385.86,3357.7 418.16,3390 709.8,3390 759.51,3340.29 759.51,2968.37 732.5,2941.36 732.5,2790.64 708.42,2766.55 605.99,2766.55 561.41,2721.98 561.41,2664.22 530.56,2633.38 331.95,2633.38 290,2675.33
  pour cut-out: 880,2182 1100,2182 1320,2182 1320,1650 690,1650 690,2182
  pour cut-out: 777.2,2411.28 777.2,2760 1165.49,2760 1165.49,2411.28
  region net P5V-Main: 1100,1840 1120,1820 1200,1820 1320,1820 1360,1860 1360,1940 1390,1970 1430,1970 1580,1970 1610,2000 1832.96,2000 1842.96,2010 1842.96,2110 1832.96,2120 1157.5,2120 1100,2062.5 1100,2040.54
  region net NetD2_1: 957,2685 1126,2685 1133.75,2677.25 1133.75,2649.75 1127,2643 988,2643 926,2581 926,2228 880,2182 880,1850 865,1835 715,1835 690,1860 690,2230.55 775,2315.55 775,2623.75 794.25,2643 915,2643
  region net GND: 7.5,3862.5 7.5,27.5 7.5,7.5 3862.5,7.5 3882.5,7.5 3882.5,3882.5 3862.5,3882.5 2900,3882.5 2900,3862.5 3862.5,3862.5 3862.5,27.5 27.5,27.5 27.5,3862.5 2500,3862.5 2500,3882.5 7.5,3882.5
  region: 0,3890
  region: 982.01,1106.11
  pour cut-out: 3920.54,1420.95
  pour cut-out: 3920.54,1420.95
  region: 310.86,2890.54
Bottom Layer:
  region net GND: 7.5,3862.5 7.5,27.5 7.5,7.5 3862.5,7.5 3882.5,7.5 3882.5,3882.5 3862.5,3882.5 2900,3882.5 2900,3862.5 3862.5,3862.5 3862.5,27.5 27.5,27.5 27.5,3862.5 2500,3862.5 2500,3882.5 7.5,3882.5
Multi-Layer:
  pour cut-out: 1900,3862.5 2000,3862.5 2000,2775 3050,2775 3050,2675 1900,2675
  pour cut-out: 1900,2675 1850,2675 1850,1900 2000,1900 2000,2700 1900,2700
  pour cut-out: 27.5,2250 690,2250 690,1650 1320,1650 1320,1600 615.98,1600 615.98,2200 27.5,2200
  pour cut-out: 3862.5,2310 3862.5,2240 3200,2240 3200,2675 3025,2675 3025,3862.5 3125,3862.5 3125,2775 3300,2775 3300,2310

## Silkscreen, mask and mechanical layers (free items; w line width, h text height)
Top Overlay:
  drawing of 802 lines, arcs and shapes, not listed
  text "-" at 453.14,3701.01 h393.7
  text "-" at 3209.05,3701.01 h393.7
  text "FEMALE" at 738.57,3563.02 h70.87 r270
  text "FEMALE" at 3133.57,3146.02 h70.87 r90
  text "+BAT" at -3.14,2998.54 h157.48
  text "+SOLAR" at 3481.86,2995.54 h118.11
  text "+" at 571.25,2884.65 h196.85 r90
  text "+" at 3409.84,2884.08 h196.85 r90
  text "SENSOR NODE / V3.1" at 2653.27,2749.78 h47.24
  text "-" at 571.25,2480.54 h275.59 r90
  text "-" at 581.09,2480.54 h275.59 r90
  text "-" at 3409.84,2480.54 h275.59 r90
  text "RESET" at 1116.24,2368.8 h31.5
  text "T1" at 482.68,2149.02 h31.5 r90
  text "T1" at 1564.86,2096.93 h31.5 r90
  text "G" at 1941.24,1058.93 h31.5 r90
  text "TX" at 1944.24,947.93 h31.5 r90
  text "RX" at 1944.24,843.93 h31.5 r90
Bottom Overlay:
  drawing of 873 lines, arcs and shapes, not listed
  text "SENSOR NODE V3.1 / Model: MultiSensor_LR433.1W / QTech Vietnam / 09/2019 / fps.qtechvietnam@gmail.com" at 2063.13,2946.65 h39.37
  text "CONNECTOR MAPPING" at 1535.94,1604.55 h39.37
  text "DS 01" at 1417.83,1515.97 h39.37
  text "1" at 1535.82,1515.97 h39.37
  text "SOLDER JUMP" at 2628.34,1515.97 h35.43
  text "TEST POINT" at 3041.72,1515.97 h39.37
  text "Back side" at 807.47,1456.92 h39.37
  text "DS 02" at 1417.83,1437.23 h39.37
  text "2" at 1535.82,1437.23 h39.37
  text "J7" at 2608.65,1437.23 h39.37
  text "VCC" at 2844.87,1437.23 h39.37
  text "T1" at 3022.04,1437.23 h39.37
  text "Wind Direction" at 1417.83,1358.49 h39.37
  text "3" at 1535.94,1358.49 h39.37
  text "J8" at 2608.65,1358.49 h39.37
  text "VBAT" at 2864.56,1358.49 h39.37
  text "T2" at 3022.04,1358.49 h39.37
  text "Enable Prog." at 2480.7,1348.65 h39.37
  text "Wind Speed" at 1417.83,1279.75 h39.37
  text "4" at 1535.94,1279.75 h39.37
  text "Dis. Q1" at 2490.54,1279.75 h39.37
  text "J11" at 2628.34,1279.75 h39.37
  text "VSEN" at 2864.56,1279.75 h39.37
  text "T4" at 3022.04,1279.75 h39.37
  text "8" at 1782.01,1269.91 h118.11
  text "Water Pressure" at 1417.83,1201.01 h39.37
  text "5" at 1535.94,1201.01 h39.37
  text "LED OFF" at 2500.39,1201.01 h39.37
  text "J12" at 2628.34,1201.01 h39.37
  text "VSOLAR" at 2894.09,1201.01 h39.37
  text "T5" at 3022.04,1201.01 h39.37
  text "1" at 807.6,1191.17 h118.11
  text "Air Pressure" at 1417.83,1122.27 h39.37
  text "6" at 1535.94,1122.27 h39.37
  text "GND" at 2844.87,1122.27 h39.37
  text "T6" at 3022.04,1122.27 h39.37
  text "Manual" at 2352.87,1063.59 h39.37
  text "SHT30 Soil" at 1417.83,1043.53 h39.37
  text "7" at 1535.94,1043.53 h39.37
  text "BUTTON" at 2726.76,1023.85 h47.24
  text "SHT30 Humidity" at 1417.83,964.79 h39.37
  text "8" at 1535.94,964.79 h39.37
  text "2" at 807.6,945.11 h118.11
  text "7" at 1782.01,945.11 h118.11
  text "RESET" at 2943.3,945.11 h39.37
  text "3" at 984.76,769.99 h118.11
  text "4" at 1230.83,769.99 h118.11
  text "5" at 1476.89,769.99 h118.11
  text "6" at 1722.95,769.99 h118.11
  text "Front side" at 2933.46,699.04 h39.37
  text "INPUT Voltage range (BAT Connector) : 8-30V DC / INPUT SOLAR : Use SOLAR CHARGER board" at 2283.85,590.78 h39.37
